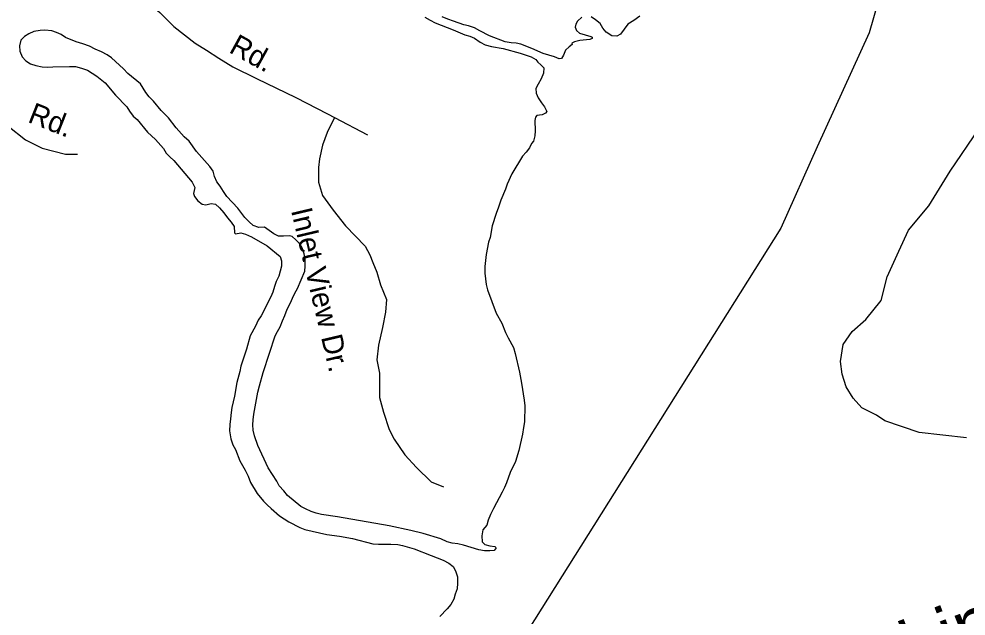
# Model space of a CAD drawing. Extents: x 1945482 to 2853149, y 66427 to 1015778.
# Drawn here: x 2352907 to 2355850, y 162514 to 164370 of the extents above; entities that cross this region are included whole.
import ezdxf

# ---------------------------------------------------------------- set-up
doc = ezdxf.new("R2010")
doc.units = 0
for name, color, linetype in [('Old_Level_10', 7, 'Continuous'), ('Old_Level_21', 7, 'Continuous'), ('Old_Level_35', 7, 'Continuous'), ('Old_Level_48', 7, 'Continuous'), ('Old_Level_49', 7, 'Continuous'), ('Old_Level_60', 7, 'Continuous'), ('Old_Level_61', 7, 'Continuous')]:
    doc.layers.add(name, color=color, linetype=linetype)

msp = doc.modelspace()

# ---------------------------------------------------------------- linework, layer by layer
at = {"layer": 'Old_Level_35'}
for points in [[(2352834.4, 164888.8), (2352868.8, 164876.2), (2352978.5, 164840.5), (2353051.3, 164817.5), (2353118.5, 164687.8), (2353150.9, 164631), (2353172.3, 164589.9), (2353191.8, 164552.9), (2353204.9, 164527.2), (2353217.4, 164511.9), (2353244.9, 164478.9), (2353275.9, 164449.9), (2353300.8, 164426.9), (2353344.2, 164390.6), (2353388, 164346.3), (2353454, 164295.1), (2353489.1, 164272.6), (2353528.1, 164247.8), (2353571.2, 164221.7), (2353644.5, 164184.5), (2353767, 164125.4), (2353865.1, 164075.1), (2353887.7, 164063.3)], [(2352804.3, 164104.2), (2352872.1, 164038.3), (2352927, 163994.3), (2352978.4, 163968.6), (2353051.7, 163950.2), (2353088.3, 163950.2)], [(2353887.7, 164063.3), (2353864.6, 164017.1), (2353849.6, 163977.9), (2353840.5, 163935.6), (2353837.5, 163908.5), (2353837.5, 163863.2), (2353849.6, 163821), (2353882.7, 163775.7), (2353921.9, 163727.4), (2353982.3, 163664), (2353997.3, 163636.9), (2354006.4, 163612.7), (2354018.4, 163582.5), (2354030.5, 163543.3), (2354048.6, 163498), (2354045.6, 163458.8), (2354036.5, 163410.5), (2354024.5, 163356.2), (2354018.4, 163310.9), (2354027.5, 163268.7), (2354027.5, 163232.5), (2354027.5, 163193.2), (2354039.6, 163148), (2354057.6, 163093.6), (2354072.7, 163063.4), (2354105.9, 163015.2), (2354142.1, 162975.9), (2354187.3, 162930.7), (2354226.5, 162915.6)], [(2353887.7, 164063.3), (2353989.8, 164010.1)]]:
    msp.add_lwpolyline(points, dxfattribs=at)
at = {"layer": 'Old_Level_48'}
for points in [[(2356762.8, 168530.5), (2355549, 164326.5), (2355387.6, 163972.4)], [(2355387.6, 163972.4), (2355274.4, 163720), (2354014, 161715)]]:
    msp.add_lwpolyline(points, dxfattribs=at)
at = {"layer": 'Old_Level_49'}
for points in [[(2356762.8, 168530.5), (2355549, 164326.5), (2355387.6, 163972.4)], [(2355387.6, 163972.4), (2355274.4, 163720), (2354014, 161715)]]:
    msp.add_lwpolyline(points, dxfattribs=at)
at = {"layer": 'Old_Level_60'}
for points in [[(2354167.7, 164376), (2354184.7, 164366), (2354200, 164358.3), (2354256.5, 164336.1), (2354292.5, 164321), (2354308.2, 164316.9), (2354322.7, 164309.9), (2354339.5, 164297.6), (2354355.5, 164289.7), (2354375, 164284.3), (2354411.5, 164277.8), (2354464, 164264.1), (2354498.2, 164252.8), (2354512.5, 164244.1), (2354519.5, 164236)], [(2354655.5, 164375.8), (2354642.5, 164363.5), (2354637.2, 164354.2), (2354635.7, 164344.3), (2354639.5, 164334.6), (2354648.5, 164326.1), (2354683.7, 164315.9), (2354688, 164313.3), (2354687.7, 164309.8), (2354681, 164305.8), (2354650.2, 164303), (2354633.5, 164299.1), (2354625, 164295.3), (2354625.7, 164290.2), (2354616.2, 164283.8), (2354605.2, 164272.7), (2354599, 164257.6), (2354592.7, 164247.6), (2354585.2, 164246), (2354570.7, 164252.1), (2354536, 164263.1), (2354500.2, 164278.7), (2354466.5, 164291.2), (2354451.5, 164294.8), (2354436.2, 164295.5), (2354417.5, 164298.9), (2354369.5, 164317.6), (2354338.5, 164332.8), (2354322, 164342.1), (2354304.2, 164348.5), (2354289.2, 164351.8), (2354257.2, 164362.7), (2354239.7, 164369.1), (2354222.2, 164377)], [(2354836.5, 164378.3), (2354817, 164364.8), (2354798.5, 164353.8), (2354775.7, 164323.1), (2354764.5, 164316.1), (2354749, 164317.3), (2354731.5, 164328.9), (2354721.5, 164341.9), (2354712.5, 164356.2), (2354698.2, 164367.7), (2354685, 164376.5)], [(2353084.7, 164298.7), (2353051.5, 164312.8), (2353037.7, 164321.8), (2353023.7, 164328.3), (2353009, 164333.3), (2352987.5, 164335.4), (2352972.2, 164334.3), (2352953, 164330.7), (2352938, 164323.8), (2352924, 164315.5), (2352912.7, 164304.1), (2352908, 164286.6), (2352909, 164269.6), (2352916.7, 164252.5), (2352928, 164239.6), (2352942.2, 164231), (2352959, 164225.6), (2352978.5, 164221.6), (2352994.7, 164220.1), (2353012, 164221.6), (2353063.7, 164222.5), (2353082.5, 164221.8), (2353101.2, 164217.3), (2353119.7, 164210.4), (2353149, 164192.3), (2353174.5, 164171.3), (2353207, 164133.1), (2353218.5, 164122.1), (2353230.5, 164107.9), (2353242.2, 164097.1), (2353250, 164083.4), (2353261.5, 164068.3), (2353274.2, 164057.4), (2353306.5, 164018.5), (2353331.2, 163995.2), (2353355.5, 163967.5), (2353364.7, 163952.8), (2353375.2, 163941.7), (2353388.2, 163930.5), (2353445.2, 163862.4), (2353453.2, 163846.4), (2353449.2, 163827.6), (2353452.5, 163818.5), (2353462.7, 163804.7), (2353476, 163794.4), (2353487.2, 163791.9), (2353504, 163796.3), (2353517.5, 163794.3), (2353529.7, 163782.8), (2353543.2, 163767.2), (2353554.5, 163752), (2353566, 163738.3), (2353575.2, 163725.3), (2353576.5, 163705.7), (2353580, 163701.9), (2353596, 163705.4), (2353610.5, 163701.2), (2353629.2, 163692.8), (2353678, 163664.7), (2353718.7, 163631.8), (2353722.2, 163618.4), (2353723, 163601.8), (2353714.2, 163570.3), (2353706.5, 163554.2), (2353700.5, 163538.7), (2353695.2, 163520.8), (2353689.2, 163506), (2353659.5, 163447.3), (2353650.5, 163434.1), (2353641.5, 163415.1), (2353625.5, 163384.9), (2353614, 163343.9), (2353596.5, 163291.2), (2353593, 163273.8), (2353584, 163239.8), (2353576.5, 163197.1), (2353568.2, 163162.7), (2353566, 163146.4), (2353564.5, 163127.5), (2353561.7, 163109), (2353561.2, 163089.3), (2353564.7, 163065.2), (2353571.5, 163045.7), (2353580, 163031.6), (2353593, 162996.3), (2353610.2, 162967), (2353619.2, 162948.3), (2353626.5, 162929.1), (2353646.7, 162895), (2353666.2, 162870.9), (2353677.7, 162859.5), (2353691, 162848.8), (2353716.5, 162825.7), (2353745.2, 162806.6), (2353779.5, 162788.8), (2353795.5, 162783), (2353863.7, 162768), (2353902.7, 162762.6), (2353943.5, 162754.7)], [(2353666, 163270.9), (2353685, 163331.5), (2353703, 163384.9), (2353710, 163398.2), (2353719, 163412.7), (2353725.7, 163431.9), (2353733.2, 163448.1), (2353740.5, 163467.5), (2353751, 163487.2), (2353756.5, 163502.2), (2353763.7, 163517.3), (2353772.5, 163532.2), (2353795, 163586.5), (2353796, 163602.1), (2353795.7, 163621.8), (2353793.2, 163639.5), (2353786.7, 163658.1), (2353779, 163671.9), (2353767.5, 163683.7), (2353756, 163693.7), (2353747.2, 163695.8), (2353728.7, 163694.4), (2353713.2, 163694.8), (2353698.5, 163702.4), (2353670, 163722.6), (2353651.7, 163722.3), (2353634.7, 163728.1), (2353622, 163739.9), (2353609.2, 163753.2), (2353586.5, 163781.6), (2353552.5, 163818.3), (2353542, 163833.3), (2353532.5, 163850), (2353521.7, 163863.5), (2353514.2, 163880.1), (2353510.2, 163896.9), (2353499.5, 163911.7), (2353458.5, 163958.4), (2353435.2, 163990), (2353419.7, 164004.1), (2353395.2, 164032.1), (2353371.2, 164062.4), (2353349.2, 164085.1), (2353325.2, 164115), (2353311.5, 164128.2), (2353301.2, 164141.4), (2353284.7, 164168.7), (2353245, 164200.1), (2353231.5, 164214.5), (2353194.5, 164249.6), (2353181, 164258.5), (2353163.5, 164267.8), (2353143.7, 164276.6), (2353126.2, 164285.7), (2353105.7, 164293), (2353084.7, 164298.7)], [(2354519.5, 164236), (2354529, 164227.9), (2354538.2, 164217.9), (2354537, 164201.2), (2354529.5, 164184.1), (2354519.7, 164167.1), (2354513, 164153.5), (2354513.7, 164139.7), (2354519.7, 164124.7), (2354530.2, 164109.5), (2354540, 164097.2), (2354547.2, 164082.2), (2354543, 164077.3), (2354532.5, 164071.9), (2354516, 164069.9), (2354512, 164065.2), (2354510, 164054.5), (2354510.5, 164022.4), (2354509.7, 164006.5), (2354506, 163990.2), (2354500, 163982.8), (2354493, 163969.6), (2354483, 163956.2), (2354471.5, 163943.8), (2354438.2, 163888.9), (2354424, 163857), (2354418.2, 163841), (2354404, 163807), (2354397, 163785.4), (2354389.2, 163765), (2354377.7, 163726.5), (2354371.2, 163690.6), (2354366, 163676), (2354359, 163637.9), (2354354, 163600.9), (2354354.5, 163579.9), (2354359, 163544.7), (2354363, 163527.7), (2354389.7, 163455.1), (2354407.7, 163424.9), (2354419, 163395.8), (2354426.7, 163378.4), (2354443.5, 163348.3), (2354449, 163330.1), (2354462, 163271.8), (2354468.7, 163237.5), (2354477.2, 163184.8), (2354478.7, 163167.7), (2354478, 163117.8), (2354474.2, 163099.6), (2354472, 163079.5), (2354459.7, 163028.5), (2354449.5, 162994), (2354433.7, 162959.8), (2354421.7, 162927.8), (2354415.5, 162913.5), (2354408.5, 162898.8), (2354381.2, 162848.4), (2354372, 162829.8), (2354365, 162811.8), (2354361.2, 162796.9), (2354348.7, 162782), (2354345.2, 162763), (2354346.2, 162744.9), (2354354, 162736.1), (2354370, 162732.1), (2354385.2, 162730.5), (2354390, 162726.5), (2354383.7, 162717.7), (2354370, 162716.5), (2354353, 162717), (2354336.2, 162719.5), (2354288.7, 162734.5), (2354270.5, 162738.5), (2354253, 162741), (2354237.5, 162744.7), (2354217.7, 162753.6), (2354163.2, 162770.2), (2354125, 162779.8), (2354057.2, 162794.7), (2353896.2, 162822.2), (2353846.5, 162829.5), (2353830.2, 162833.6), (2353815, 162839.1), (2353797.7, 162846.9), (2353782.7, 162855), (2353741.5, 162888.8), (2353730, 162903.6), (2353715.5, 162919.2), (2353708.5, 162932.9), (2353681, 162974.3), (2353649.2, 163043.9), (2353639.2, 163074.7), (2353634.7, 163091.5), (2353634, 163108.5), (2353634.7, 163124.1), (2353637, 163141.6), (2353649.5, 163210.4), (2353654, 163229.8), (2353666, 163270.9)], [(2353943.5, 162754.7), (2354006, 162738.2), (2354024.2, 162737.2), (2354062.2, 162737.7), (2354083.7, 162736.5), (2354099, 162733.6), (2354135.2, 162723.1), (2354187.5, 162702), (2354225.5, 162687.7), (2354242.7, 162678.4), (2354256, 162668), (2354263.7, 162655), (2354269.5, 162636.1), (2354270, 162616.2), (2354268.2, 162599.1), (2354262, 162582), (2354258, 162566.9), (2354248.5, 162550.4), (2354237.5, 162536), (2354214.7, 162512.5)]]:
    msp.add_lwpolyline(points, dxfattribs=at)
at = {"layer": 'Old_Level_61'}
msp.add_lwpolyline([(2355851.7, 163067.9), (2355704, 163084.9), (2355597.2, 163120.9), (2355571.2, 163138.7), (2355526, 163161.3), (2355499, 163191.1), (2355477.7, 163226.4), (2355465, 163265.8), (2355459.5, 163305.6), (2355468, 163358), (2355495.7, 163399), (2355538, 163435.8), (2355586.2, 163495.2), (2355604.2, 163568.7), (2355640.5, 163648), (2355670.7, 163713.1), (2355734, 163789.4), (2355800.5, 163897), (2355891, 164029.9)], dxfattribs=at)

# ---------------------------------------------------------------- texts
at = {"layer": 'Old_Level_10'}
for s, height, rotation, p in [('Rd.', 65.62, 331.1904, (2353556.1, 164268)), ('Rd.', 65.62, 338.4711, (2352931, 164050.7)), ('Inlet View Dr.', 65.617, 283.3224, (2353751.8, 163775.1))]:
    msp.add_text(s, height=height, rotation=rotation, dxfattribs=at).set_placement(p)
at = {"layer": 'Old_Level_21'}
msp.add_text('Shinn', height=164.04, rotation=20.7438, dxfattribs=at).set_placement((2355548.2, 162279.2))

doc.saveas('drawing.dxf')
